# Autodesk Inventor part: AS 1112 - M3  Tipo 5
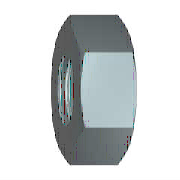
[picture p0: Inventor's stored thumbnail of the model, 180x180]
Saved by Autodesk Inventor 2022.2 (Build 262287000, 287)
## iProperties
Created: 2021-02
Part Number: AS 1112 - M3  Tipo 5
Material: Acciaio, Dolce
Description: Dadi esagonali metrici ISO, inclusi dadi sottili, dadi con intaglio e dadi a corona
Document SubType Name: Modeling
Standard: AS 1112
Designer: 18907419
Standards Organization: AS
Language: it-IT
Size Designation: M3  Tipo 5
Categories: <MemberInstance><Categories><Category DisplayName="Elementi di fissaggio" InternalName="e4da775c-781d-43d5-af7c-5136215cf5a6" Mnemonic="FSTN"><Category DisplayN
Density: 7.85 g/cm^3
Appearance: Semilucidato
IsCustomPart: 0
Author: 18907419
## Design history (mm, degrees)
sketch "Schizzo1"
  geometry: L1 (-3.175, 0)-(-1.588, 2.75); L2 (-1.588, 2.75)-(1.588, 2.75); L3 (1.588, 2.75)-(3.175, 0); L4 (3.175, 0)-(1.588, -2.75); L5 (1.588, -2.75)-(-1.588, -2.75); L6 (-1.588, -2.75)-(-3.175, 0); 2 further points
  constraints: 12 end point, 1 coincident, 1 horizontal, 11 other
  dimensions: "d0" = 6.35085 distance of L3.end L1.start (= 1.1547 x SW)
extrude "Corpo" new body sketch "Schizzo1" distance "d1" = 2.4 (= KOH); taper "d2" = 0 deg
sketch "Schizzo2"
  geometry: L1 (0, 1.588)-(0, 3.175) reference; L2 (0, 3.175)-(2.4, 3.175) reference; L3 (2.4, 1.588)-(2.4, 3.175) reference; L4 (-0.48, 0)-(2.88, 0) reference; L5 (0.246, 3.175)-(0, 2.75); L6 (2.154, 3.175)-(2.4, 2.75)
  constraints: 4 end point, 4 point on line
  dimensions: "d3" = 30 deg angle of L1 L5 (= ANG1); "d4" = 30 deg angle of L3 L6 (= ANG2); "d5" = 5.5 diameter of L5.end L4 (= SW0); "d6" = 5.5 diameter of L6.end L4 (= SW01)
revolve "Smusso1" sketch "Schizzo2" stored, may be unused: angle "d7" = 90 deg
sketch "Schizzo3"
  geometry: A1 r 2.75 centre (0, 0) between (-1.375, -2.382) and (1.375, -2.382) reference; 1 further point
  constraints: 1 coincident
hole "Filettatura" sketch "Schizzo3" at (0, 0) diameter "d25" = 2.459; stored, may be unused: countersink angle "d29" = 82 deg, drill point angle "d31" = 118 deg; dims "d26" = 6, "d27" = 4, "d28" = 2, "d30" = 8
workaxis "Work Axis1"
workplane "Work Plane1"
body "Solid1"
chamfer "Smusso2" distance "d8" = 0.27063 (= -0.5 x GD1 + 0.5 x NND); stored, may be unused: angle "d9" = 30 deg, second distance "d40" = 0.27063 (= -0.5 x GD1 + 0.5 x NND)
chamfer "Smusso3" distance "d10" = 0.27063 (= -0.5 x GD1 + 0.5 x NND); stored, may be unused: angle "d11" = 30 deg, second distance "d41" = 0.27063 (= -0.5 x GD1 + 0.5 x NND)
other parameters: "ANG1" = 30 deg [user parameter; used in 1 equation term], "ANG2" = 30 deg [user parameter; used in 1 equation term], "NND" = 3 [user parameter; used in 4 equation terms], "KOH" = 2.4 [user parameter; used in 1 equation term], "SW" = 5.5 [user parameter; used in 4 equation terms], "SW0" = 5.5 (= SW) [user parameter; used in 1 equation term], "SW01" = 5.5 (= SW) [user parameter; used in 1 equation term], "GD1" = 2.45873 (computed from THREADDIA, PTC, TOA) [user parameter; used in 4 equation terms], "d13" = 0, "d14" = 0, "d39" = 0, "d42" = 0, "GUL" = 0.27063 (= 0.541266 x PTC) [user parameter], "WFT" = 0.4 [user parameter], "THREADDIA" = 3 [user parameter; used in 1 equation term], "TOA" = 30 deg [user parameter; used in 1 equation term], "PTC" = 0.5 [user parameter; used in 4 equation terms], "E0" = 6.3525 (= 1.155 x SW) [user parameter], "GAL" = 0.27063 (= 0.541266 x PTC) [user parameter]
